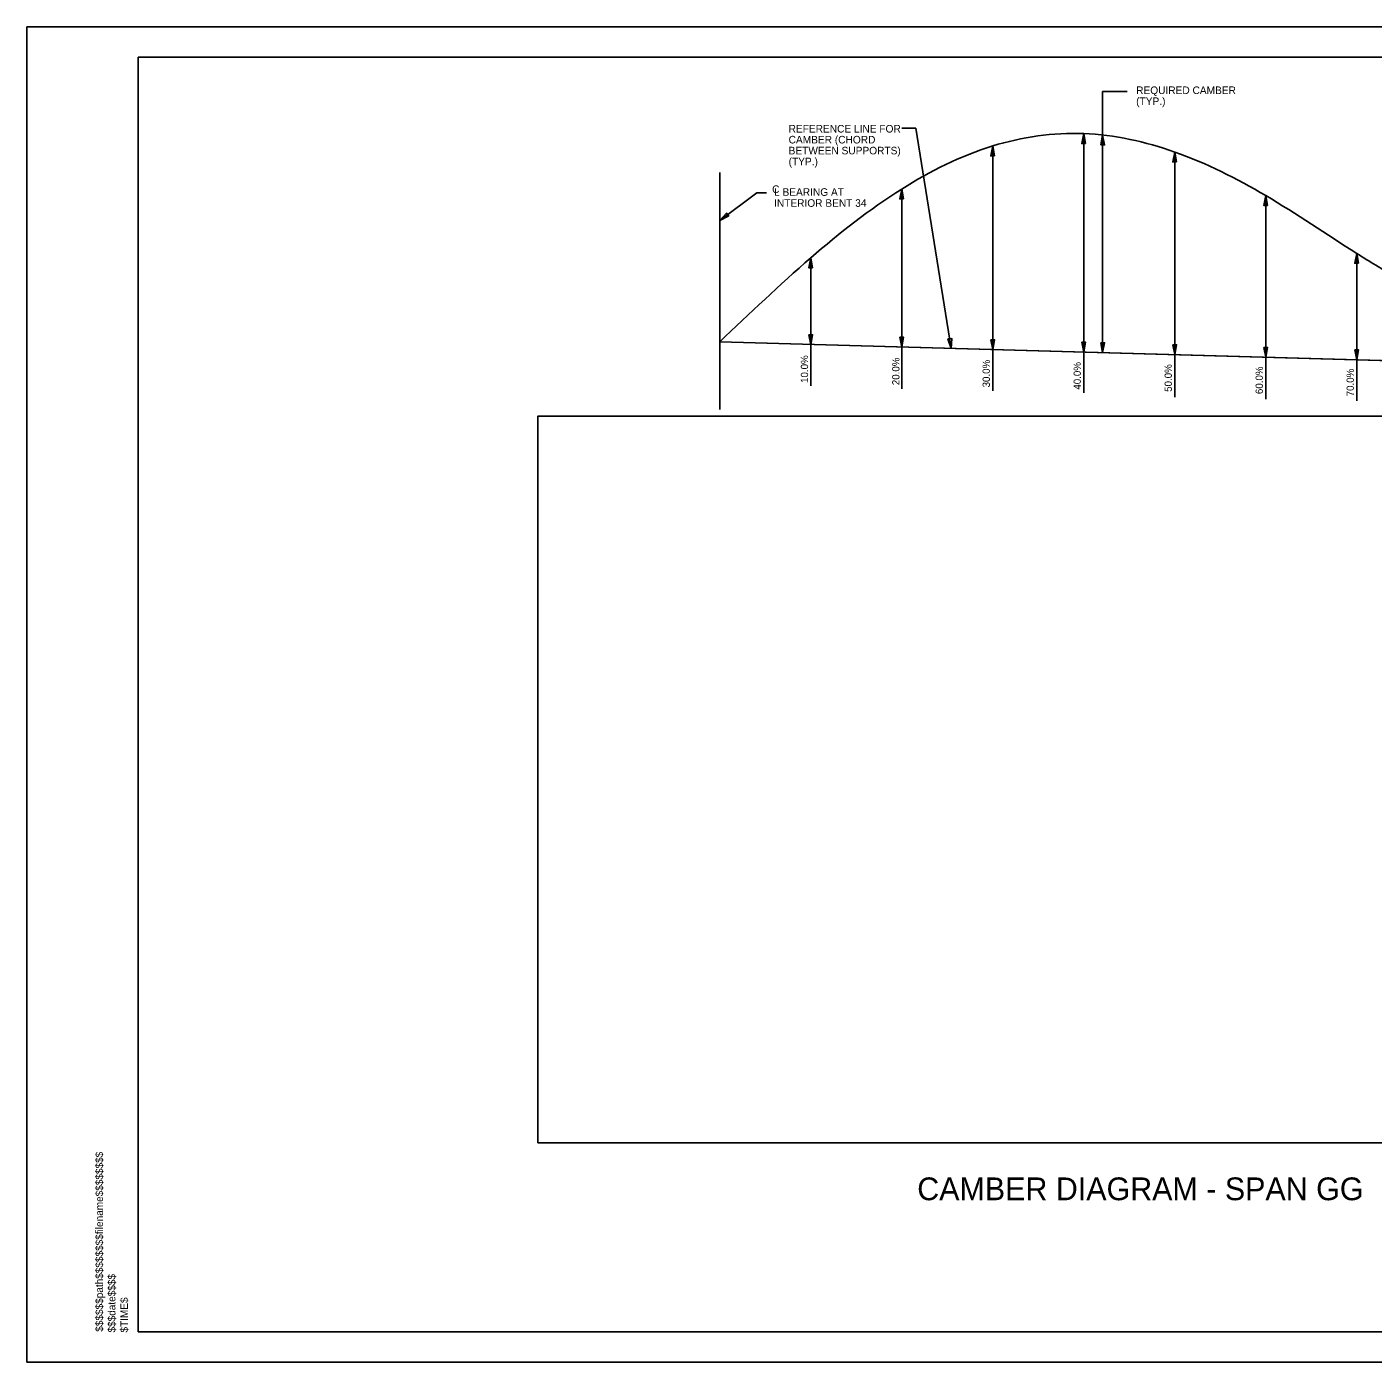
# Model space of a CAD drawing. Extents: x -133.1 to -97, y -1.7 to 20.3.
# Drawn here: x -133.14 to -110.95, y -1.69 to 20.31 of the extents above; entities that cross this region are included whole.
import ezdxf

# ---------------------------------------------------------------- set-up
doc = ezdxf.new("R2010")
doc.units = 0
for name, color, linetype in [('BR_AUTO DIMENSION', 7, 'Continuous'), ('BR_BORDER LINES', 7, 'Continuous'), ('BR_CENTER LINES', 7, 'Continuous'), ('BR_TABLE LINES', 7, 'Continuous'), ('BR_TEXT', 7, 'Continuous'), ('Default', 7, 'Continuous'), ('Level 31', 7, 'Continuous'), ('RD_SHT_ID', 7, 'Continuous')]:
    doc.layers.add(name, color=color, linetype=linetype)

msp = doc.modelspace()

# ---------------------------------------------------------------- linework, layer by layer
at = {"layer": 'BR_AUTO DIMENSION'}
for p, q in [((-115.409, 14.942), (-115.409, 19.247)), ((-115.409, 19.247), (-115.007, 19.247)), ((-118.718, 18.642), (-118.489, 18.642)), ((-118.489, 18.642), (-117.905, 15.011)), ((-121.108, 17.578), (-121.721, 17.12)), ((-120.948, 17.578), (-121.108, 17.578))]:
    msp.add_line(p, q, dxfattribs=at)
for points in [[(-115.689, 18.388), (-115.721, 18.551), (-115.752, 18.388)], [(-115.44, 18.364), (-115.409, 18.526), (-115.378, 18.364)], [(-117.189, 18.185), (-117.221, 18.348), (-117.252, 18.185)], [(-114.189, 18.086), (-114.221, 18.248), (-114.252, 18.086)], [(-118.689, 17.475), (-118.721, 17.637), (-118.752, 17.475)], [(-112.689, 17.369), (-112.721, 17.531), (-112.752, 17.369)], [(-121.573, 17.194), (-121.721, 17.12), (-121.611, 17.243)], [(-120.189, 16.341), (-120.221, 16.504), (-120.252, 16.341)], [(-111.189, 16.416), (-111.221, 16.578), (-111.252, 16.416)], [(-120.252, 15.238), (-120.221, 15.076), (-120.189, 15.238)], [(-118.752, 15.196), (-118.721, 15.034), (-118.689, 15.196)], [(-117.958, 15.168), (-117.905, 15.011), (-117.896, 15.176)], [(-117.252, 15.155), (-117.221, 14.992), (-117.189, 15.155)], [(-115.752, 15.113), (-115.721, 14.95), (-115.689, 15.113)], [(-115.44, 15.104), (-115.409, 14.942), (-115.378, 15.104)], [(-114.252, 15.071), (-114.221, 14.909), (-114.189, 15.071)], [(-112.752, 15.029), (-112.721, 14.867), (-112.689, 15.029)], [(-111.252, 14.987), (-111.221, 14.825), (-111.189, 14.987)], [(-124.721, 1.92), (-106.721, 1.92), (-106.721, 13.893), (-124.721, 13.893)]]:
    msp.add_lwpolyline(points, close=True, dxfattribs=at)
at = {"layer": 'BR_BORDER LINES'}
for p, q in [((-97.642, 19.809), (-131.308, 19.809)), ((-131.308, -1.191), (-131.308, 19.809)), ((-131.308, -1.191), (-97.642, -1.191))]:
    msp.add_line(p, q, dxfattribs=at)
at = {"layer": 'BR_CENTER LINES'}
msp.add_line((-121.721, 14.003), (-121.721, 17.91), dxfattribs=at)
at = {"layer": 'BR_TABLE LINES'}
for p, q in [((-115.721, 14.278), (-115.721, 18.551)), ((-117.221, 14.313), (-117.221, 18.348)), ((-114.221, 14.209), (-114.221, 18.248)), ((-118.721, 14.345), (-118.721, 17.637)), ((-112.721, 14.176), (-112.721, 17.531)), ((-120.221, 14.397), (-120.221, 16.504)), ((-111.221, 14.147), (-111.221, 16.578)), ((-121.721, 15.118), (-106.721, 14.699))]:
    msp.add_line(p, q, dxfattribs=at)
msp.add_spline([(-121.721, 15.118), (-120.221, 16.504), (-118.721, 17.637), (-117.221, 18.348), (-115.721, 18.551), (-114.221, 18.248), (-112.721, 17.531), (-111.221, 16.578), (-110.587, 16.184), (-109.721, 15.646), (-108.221, 14.991), (-106.721, 14.7)], degree=3, dxfattribs=at)
at = {"layer": 'Default'}
msp.add_lwpolyline([(-121.721, 15.118), (-106.721, 14.699), (-106.721, 14.699)], dxfattribs=at)
at = {"layer": 'Level 31'}
msp.add_lwpolyline([(-133.141, -1.691), (-97.141, -1.691), (-97.141, 20.309), (-133.141, 20.309)], close=True, dxfattribs=at)

# ---------------------------------------------------------------- texts
at = {"layer": 'BR_AUTO DIMENSION'}
for s, p in [('REQUIRED CAMBER', (-114.856, 19.203)), ('(TYP.)', (-114.856, 19.023)), ('REFERENCE LINE FOR', (-120.585, 18.569)), ('CAMBER (CHORD', (-120.585, 18.389)), ('BETWEEN SUPPORTS)', (-120.585, 18.209)), ('(TYP.)', (-120.585, 18.029)), ('C', (-120.857, 17.573)), ('L BEARING AT', (-120.825, 17.526)), ('INTERIOR BENT 34', (-120.825, 17.345))]:
    msp.add_text(s, height=0.125, dxfattribs=at).set_placement(p)
at = {"layer": 'BR_TEXT'}
for s, p in [('10.0%', (-120.264, 14.443)), ('20.0%', (-118.758, 14.406)), ('30.0%', (-117.268, 14.369)), ('40.0%', (-115.768, 14.332)), ('50.0%', (-114.268, 14.296)), ('60.0%', (-112.768, 14.259)), ('70.0%', (-111.268, 14.222))]:
    msp.add_text(s, height=0.12, rotation=90, dxfattribs=at).set_placement(p)
msp.add_text('CAMBER DIAGRAM - SPAN GG', height=0.375, dxfattribs=at).set_placement((-118.465, 0.976))
at = {"layer": 'RD_SHT_ID'}
for s, height, p in [('$$$$$$path$$$$$$$$filename$$$$$$$$', 0.12347, (-131.887, -1.191)), ('$$$date$$$$', 0.12347, (-131.682, -1.204)), ('$TIME$', 0.1235, (-131.477, -1.204))]:
    msp.add_text(s, height=height, rotation=90, dxfattribs=at).set_placement(p)

doc.saveas('drawing.dxf')
